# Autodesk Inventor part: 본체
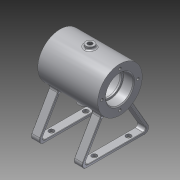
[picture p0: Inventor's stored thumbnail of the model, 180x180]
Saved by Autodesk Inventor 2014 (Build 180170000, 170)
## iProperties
Created: 2016-03
Part Number: 본체
Material: 알루미늄 6061
Document SubType Name: Modeling
Designer: basic
Density: 2.71 g/cm^3
Appearance: 알루미늄 - 평지
Mass: 213.519 g
Surface Area: 333.701 cm^2
Volume: 78.7893 cm^3
Author: basic
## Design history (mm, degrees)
sketch "스케치2"
  geometry: L1 (35, 65)-(-35, 65); L2 (35, 65)-(35, 91); L3 (35, 91)-(-35, 91); L4 (-35, 91)-(-35, 65); L5 (35, 81)-(23, 81); L6 (23, 81)-(23, 79); L7 (23, 79)-(21, 79); L8 (21, 79)-(21, 86); L9 (21, 86)-(-21, 86); L10 (-21, 86)-(-21, 79); L11 (-21, 79)-(-23, 79); L12 (-23, 79)-(-23, 81); L13 (-23, 81)-(-35, 81); 2 further points
  constraints: 26 end point, 7 parallel, 5 perpendicular, 4 equal length, 2 point on line, 1 horizontal, 1 midpoint, 1 vertical alignment
  dimensions: "d2" = 70 distance of L1.start L1.end; "d3" = 65 distance from line of point (0, 0) L1; "d4" = 14 distance between parallel lines of L1 L7; "d5" = 26 distance between parallel lines of L1 L3; "d6" = 21 distance between parallel lines of L1 L9; "d7" = 16 distance between parallel lines of L1 L5; "d8" = 42 distance between parallel lines of L10 L8; "d9" = 12 distance between parallel lines of L2 L6
revolve "회전1" sketch "스케치2" stored, may be unused: angle "d10" = 90 deg
fillet "모깎기1" dims "d11" = 0.3
chamfer "모따기1" distance "d12" = 1; stored, may be unused: second distance "d13" = 2, angle "d14" = 45 deg
chamfer "모따기2" distance "d15" = 1; stored, may be unused: second distance "d16" = 2, angle "d17" = 45 deg
fillet "모깎기2" dims "d24" = 3
node "작업 평면1"
sketch "스케치6"
  geometry: L1 (-42.594, 0)-(42.594, 0); L2 (-16.613, 45)-(-42.594, 0); L3 (16.613, 45)-(42.594, 0); L4 (0, 65)-(0, 0); L5 (-14.015, 43.5)-(-37.398, 3); L6 (-37.398, 3)-(37.398, 3); L7 (37.398, 3)-(14.015, 43.5); C1 r 20.236 at (0, 65) reference; A1 r 26 centre (0, 65) between (-16.613, 45) and (16.613, 45) reference; A2 r 26 centre (0, 65) between (-16.613, 45) and (-14.183, 43.209); A3 r 26 centre (0, 65) between (14.183, 43.209) and (16.613, 45); 1 further point
  constraints: 14 end point, 6 point on circle, 2 centre point, 2 coincident, 2 point on line, 1 equal length, 1 horizontal, 1 midpoint, 1 perpendicular, 2 other
  dimensions: "d26" = 30 deg angle of L4 L2; "d27" = 30 deg angle of L3 L4; "d28" = 45 distance from line of L1 L3.start; "d29" = 3 distance between parallel lines of L2 L5
extrude "돌출1" join sketch "스케치6" distance "d30" = 10; taper "d31" = 0 deg
fillet "모깎기3" dims "d32" = 5
fillet "모깎기4" dims "d33" = 3
fillet "모깎기5" dims "d34" = 0.5
fillet "모깎기6" dims "d35" = 3
sketch "스케치7" dims "d36" = 42
  geometry: L1 (0, 0)-(0, -21); C1 r 17 at (0, 0) reference; 2 further points
  constraints: 2 coincident, 2 end point, 1 vertical, 1 vertical alignment, 2 other
hole "구멍1" sketch "스케치7" at (0, -21) diameter "d37" = 3.242; stored, may be unused: countersink angle "d41" = 90 deg, drill point angle "d43" = 118 deg; dims "d38" = 8, "d39" = 4, "d40" = 2, "d42" = 10
node "작업 평면2"
sketch "스케치8"
  geometry: C1 r 5 at (0, 0); 1 further point
  constraints: 1 centre point, 1 coincident
  dimensions: "d48" = 10 diameter of C1
extrude "돌출2" join sketch "스케치8" stored distance "d49" = 10; taper "d50" = 0 deg
fillet "모깎기7" dims "d51" = 2
sketch "스케치9"
  geometry: C1 r 5 at (0, 0) reference; 1 further point
  constraints: 1 coincident
hole "구멍2" sketch "스케치9" at (0, 0) diameter "d52" = 5.188; stored, may be unused: countersink angle "d56" = 90 deg, drill point angle "d58" = 118 deg; dims "d53" = 20, "d54" = 4, "d55" = 2, "d57" = 10
node "작업 평면5"
sketch "스케치12"
  geometry: L1 (-35, 0)-(35, 0) reference; L2 (-20.5, -42.258)-(-29.5, -42.258) reference; L3 (-30, -41.258)-(-30, -37.258) reference; L4 (-29.5, -36.258)-(-20.5, -36.258) reference; L5 (-20, -37.258)-(-20, -41.258) reference; L6 (-20, -62.5)-(-20, -64.5) reference; L7 (-20.5, -65)-(-29.5, -65) reference; L8 (-30, -64.5)-(-30, -62.5) reference; L9 (-29.5, -62)-(-20.5, -62) reference; L10 (-35, -26)-(-35, 26) reference; L11 (-35, 0)-(35, 0) reference; L12 (-20.5, -42.258)-(-29.5, -42.258) reference; L13 (-30, -41.258)-(-30, -37.258) reference; L14 (-29.5, -36.258)-(-20.5, -36.258) reference; L15 (-20, -37.258)-(-20, -41.258) reference; L16 (-20, -62.5)-(-20, -64.5) reference; L17 (-20.5, -65)-(-29.5, -65) reference; L18 (-30, -64.5)-(-30, -62.5) reference; L19 (-29.5, -62)-(-20.5, -62) reference; L20 (30, -42.258)-(20, -42.258) reference; L21 (20, -42.258)-(20, -36.258) reference; L22 (20, -36.258)-(30, -36.258) reference; L23 (30, -36.258)-(30, -42.258) reference; L24 (30, -62)-(30, -65) reference; L25 (30, -65)-(20, -65) reference; L26 (20, -65)-(20, -62) reference; L27 (20, -62)-(30, -62) reference; L28 (30, -42.258)-(20, -42.258) reference; L29 (20, -42.258)-(20, -36.258) reference; L30 (20, -36.258)-(30, -36.258) reference; L31 (30, -36.258)-(30, -42.258) reference; L32 (30, -62)-(30, -65) reference; L33 (30, -65)-(20, -65) reference; L34 (20, -65)-(20, -62) reference; L35 (20, -62)-(30, -62) reference; A1 r 0.5 centre (-20.5, -64.5) between (-20.5, -65) and (-20, -64.5) reference; A2 r 0.5 centre (-29.5, -64.5) between (-30, -64.5) and (-29.5, -65) reference; A3 r 0.5 centre (-29.5, -62.5) between (-29.5, -62) and (-30, -62.5) reference; A4 r 0.5 centre (-20.5, -62.5) between (-20, -62.5) and (-20.5, -62) reference; A5 r 0.5 centre (-20.5, -64.5) between (-20.5, -65) and (-20, -64.5) reference; A6 r 0.5 centre (-29.5, -64.5) between (-30, -64.5) and (-29.5, -65) reference; A7 r 0.5 centre (-29.5, -62.5) between (-29.5, -62) and (-30, -62.5) reference; A8 r 0.5 centre (-20.5, -62.5) between (-20, -62.5) and (-20.5, -62) reference; 10 further points; 8 other entities
  constraints: 9 other
  dimensions: "d61" = 35 distance from line of L10 point (0, 0); "d62" = 26 vertical distance of point (0, 0) L10.end
feature "엠보싱1" sketch "스케치12" dims "d2" = 70, "d3" = 65, "d4" = 14, "d5" = 26, "d6" = 21, "d7" = 16, "d8" = 42, "d9" = 12, "d63" = 0.5, "d64" = 0
sketch "스케치15"
  geometry: L1 (-2.594, 94)-(-2.594, 85.839) reference; L2 (2.594, 85.839)-(2.594, 94) reference; L3 (2.594, 94)-(5, 94) reference; L4 (5, 94)-(5, 92.111) reference; L5 (25.891, 67.381)-(26.389, 67.427) reference; L6 (26.424, 67.007)-(25.925, 66.969) reference; L7 (-5, 92.111)-(-5, 94) reference; L8 (-5, 94)-(-2.594, 94) reference; L9 (0, 65)-(0, 39); L10 (0, 65)-(-6.729, 39.886); A1 r 21 centre (0, 65) between (-2.594, 85.839) and (2.594, 85.839) reference; A2 r 26 centre (0, 65) between (25.891, 67.381) and (6.5, 90.174) reference; A3 r 26.5 centre (0, 65) between (26.424, 67.007) and (26.389, 67.427) reference; A4 r 26 centre (0, 65) between (-6.5, 90.174) and (25.925, 66.969) reference; 1 further point
  constraints: 4 end point, 2 point on circle, 1 perpendicular, 2 other
  dimensions: "d70" = 15 deg angle of L9 L10
  node "절단 모서리 투영7"
node "작업 평면7"
sketch "스케치16"
  geometry: C1 r 6 at (0, 0); 1 further point
  constraints: 1 centre point
  dimensions: "d71" = 12 diameter of C1
extrude "돌출3" join sketch "스케치16" stored distance "d72" = 10; taper "d73" = 0 deg
sketch "스케치17"
  geometry: C1 r 6 at (0, 0); A1 r 6 centre (0, 0) between (-6, 0) and (6, 0) reference; 1 further point
  constraints: 1 centre point, 1 coincident
  dimensions: "d74" = 12 diameter of C1
extrude "돌출4" join sketch "스케치17" distance "d75" = 3; taper "d76" = 0 deg
fillet "모깎기8" dims "d77" = 2
sketch "스케치18"
  geometry: C1 r 6 at (0, 0) reference; 2 further points
  constraints: 1 coincident
hole "구멍3" sketch "스케치18" at (0, 0) diameter "d78" = 5.188; stored, may be unused: countersink angle "d82" = 90 deg, drill point angle "d84" = 118 deg; dims "d79" = 20, "d80" = 4, "d81" = 2, "d83" = 10
fillet "모깎기10" dims "d106" = 5
fillet "모깎기13" dims "d109" = 3
fillet "모깎기14" dims "d110" = 0.5
fillet "모깎기15" dims "d111" = 3
sketch "스케치21"
  geometry: L1 (-0.5, 66.206)-(-0.5, 70.167) reference; L2 (0, 70.718)-(9, 70.718) reference; L3 (9.5, 70.167)-(9.5, 66.206) reference; L4 (9, 64.403)-(9, 0) reference; L5 (0, 0)-(9, 0) reference; L6 (-0.5, -5.763)-(-0.5, -1.803) reference; L7 (9, -6.315)-(0, -6.315) reference; L8 (9.5, -1.803)-(9.5, -5.763) reference; L9 (0, 64.403)-(9, 64.403) reference; L10 (0, 64.403)-(0, 0) reference; L11 (49.5, 66.206)-(49.5, 70.167) reference; L12 (50, 70.718)-(59, 70.718) reference; L13 (59.5, 70.167)-(59.5, 66.206) reference; L14 (59, 64.403)-(59, 0) reference; L15 (59, 0)-(50, 0) reference; L16 (49.5, -5.763)-(49.5, -1.803) reference; L17 (59, -6.315)-(50, -6.315) reference; L18 (59.5, -1.803)-(59.5, -5.763) reference; L19 (59, 64.403)-(50, 64.403) reference; L20 (50, 64.403)-(50, 0) reference; C1 r 3 at (4.5, 52.202); C2 r 3 at (4.5, 12.202); C3 r 3 at (54.5, 52.202); C4 r 3 at (54.5, 12.202); 4 further points
  constraints: 4 centre point, 4 vertical alignment, 3 midpoint, 16 other
  dimensions: "d112" = 6 diameter of C1; "d113" = 6 diameter of C2; "d114" = 6 diameter of C3; "d115" = 6 diameter of C4; "d116" = 20 vertical distance of point (29.5, 32.202) C1.centre; "d117" = 40 distance of C1.centre C2.centre; "d118" = 20 vertical distance of point (29.5, 32.202) C3.centre; "d119" = 40 distance of C4.centre C3.centre
extrude "돌출7" cut sketch "스케치21" stored distance "d120" = 3; taper "d121" = 0 deg
node "솔리드1"
mirror "대칭1"
pattern_circular "원형 패턴1" dims angle "d45" = 360 deg
mirror "대칭2"
node "절단 모서리 투영1"
node "절단 모서리 투영4"
node "절단 모서리 투영5"
node "절단 모서리 투영10"
other parameters: "d47" = 94
